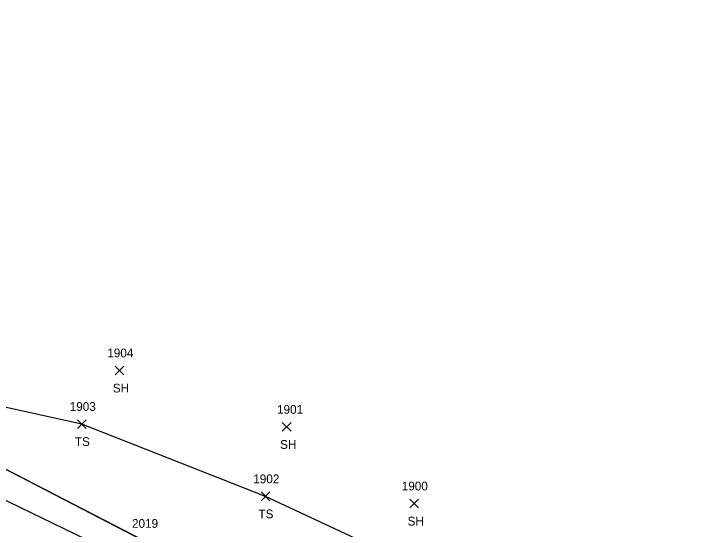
# Model space of a CAD drawing. Extents: x 1415642 to 1422021, y 544543 to 547232.
# Drawn here: x 1415966.4 to 1416123.6, y 547017.8 to 547135.3 of the extents above; entities that cross this region are included whole.
import ezdxf

# ---------------------------------------------------------------- set-up
doc = ezdxf.new("R2010")
doc.units = 0
for name, color, linetype in [('L_A', 7, 'Continuous'), ('L_I', 7, 'Continuous'), ('L_TIC', 7, 'Continuous'), ('LAWA', 7, 'Continuous'), ('LELB', 7, 'Continuous'), ('LFNC', 7, 'Continuous')]:
    doc.layers.add(name, color=color, linetype=linetype)

msp = doc.modelspace()

# ---------------------------------------------------------------- linework, layer by layer
at = {"layer": 'L_TIC'}
for points in [[(1415989.47, 547052.97), (1415991.47, 547054.97)], [(1415991.47, 547052.97), (1415989.47, 547054.97)], [(1415980.89, 547040.76), (1415982.89, 547042.76)], [(1415982.89, 547040.76), (1415980.89, 547042.76)], [(1416027.61, 547040.11), (1416029.61, 547042.11)], [(1416029.61, 547040.11), (1416027.61, 547042.11)], [(1416022.76, 547024.27), (1416024.76, 547026.27)], [(1416024.76, 547024.27), (1416022.76, 547026.27)], [(1416056.71, 547022.63), (1416058.71, 547024.63)], [(1416058.71, 547022.63), (1416056.71, 547024.63)]]:
    msp.add_lwpolyline(points, dxfattribs=at)
at = {"layer": 'LAWA'}
for points in [[(1416240.56, 546960.73), (1416233.2, 546953.27), (1416224.51, 546941.93), (1416214.85, 546929.39), (1416199.95, 546923.14), (1416193.46, 546920.24), (1416179.13, 546920.7), (1416159.93, 546927.15), (1416126.32, 546945.38), (1416100.02, 546952.8), (1416028.43, 546991.66), (1415993.05, 547010.51), (1415954.88, 547028.97)], [(1416240.56, 546960.73), (1416233.2, 546953.27), (1416224.51, 546941.93), (1416214.86, 546929.39), (1416199.95, 546923.14), (1416193.46, 546920.24), (1416179.13, 546920.7), (1416159.93, 546927.15), (1416126.32, 546945.39), (1416100.02, 546952.81), (1416028.43, 546991.66), (1415993.05, 547010.51), (1415954.88, 547028.96)]]:
    msp.add_lwpolyline(points, dxfattribs=at)
at = {"layer": 'LELB'}
for points in [[(1416157.94, 546955.38), (1416155.92, 546957.27), (1416135.55, 546960.79), (1416132.49, 546973.78), (1416110.9, 546979.13), (1416081.52, 546992.2), (1416051.18, 547012.47), (1416023.77, 547025.27), (1415981.89, 547041.76), (1415959.36, 547046.67), (1415931.91, 547061.5), (1415911.94, 547074.57), (1415881.06, 547095.53), (1415867.9, 547121.94)], [(1416157.94, 546955.38), (1416155.92, 546957.27), (1416135.55, 546960.79), (1416132.49, 546973.77), (1416110.9, 546979.12), (1416081.52, 546992.2), (1416051.18, 547012.47), (1416023.76, 547025.27), (1415981.89, 547041.76), (1415959.36, 547046.67), (1415931.91, 547061.5), (1415911.93, 547074.57), (1415881.06, 547095.53), (1415867.9, 547121.93)]]:
    msp.add_lwpolyline(points, dxfattribs=at)
at = {"layer": 'LFNC'}
for points in [[(1416067.58, 546984.06), (1416031.2, 546999.34), (1415996.11, 547015.1), (1415957.45, 547035.03), (1415922.34, 547052.78), (1415883.85, 547076.17), (1415852.09, 547094.57), (1415823.18, 547113.63), (1415819.4, 547116.14), (1415815.46, 547118.48), (1415790.83, 547135.32)], [(1416067.58, 546984.06), (1416031.2, 546999.34), (1415996.12, 547015.09), (1415957.45, 547035.03), (1415922.34, 547052.78), (1415883.85, 547076.17), (1415852.09, 547094.57), (1415823.18, 547113.64), (1415819.41, 547116.14), (1415815.45, 547118.48), (1415790.83, 547135.32)]]:
    msp.add_lwpolyline(points, dxfattribs=at)

# ---------------------------------------------------------------- texts
at = {"layer": 'L_A'}
for s, p in [('SH', (1415988.95, 547048.97)), ('TS', (1415980.3, 547036.76)), ('SH', (1416027.1, 547036.11)), ('TS', (1416022.17, 547020.27)), ('SH', (1416056.19, 547018.63))]:
    msp.add_text(s, height=2, dxfattribs=at).set_placement(p)
at = {"layer": 'L_I'}
for s, p in [('1904', (1415987.69, 547056.97)), ('1903', (1415979.12, 547044.76)), ('1901', (1416026.41, 547044.11)), ('1902', (1416020.99, 547028.27)), ('1900', (1416054.85, 547026.63)), ('2019', (1415993.33, 547018.1))]:
    msp.add_text(s, height=2, dxfattribs=at).set_placement(p)

doc.saveas('drawing.dxf')
